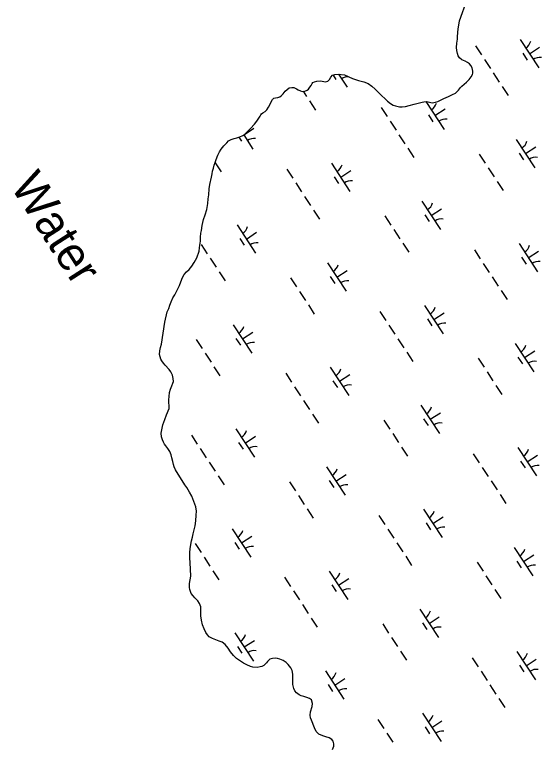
# Model space of a CAD drawing. Extents: x 3945642 to 3966284, y 206476 to 228921.
# Drawn here: x 3957251 to 3958027, y 210144 to 211224 of the extents above; entities that cross this region are included whole.
import ezdxf

# ---------------------------------------------------------------- set-up
doc = ezdxf.new("R2010")
doc.units = 0
doc.layers.add('V-RIVR-IDEN', color=7, linetype='Continuous')
doc.layers.add('V-WETL-SWMP', color=7, linetype='Continuous')

msp = doc.modelspace()

# ---------------------------------------------------------------- linework, layer by layer
at = {"layer": 'V-WETL-SWMP'}
for p, q in [((3957906.8, 211214.9), (3957917.9, 211247.1)), ((3957905.6, 211208.7), (3957906.8, 211214.9)), ((3957904.9, 211203.2), (3957905.6, 211208.7)), ((3957903.9, 211191.5), (3957904.3, 211197.7)), ((3957904.3, 211197.7), (3957904.9, 211203.2)), ((3957902.9, 211181.9), (3957903.5, 211188)), ((3957903.5, 211188), (3957903.9, 211191.5)), ((3957996, 211187.3), (3958023.4, 211145.4)), ((3957902.4, 211175.8), (3957902.9, 211181.9)), ((3957902.7, 211171), (3957902.4, 211175.8)), ((3957930.2, 211178.1), (3957939, 211164.8)), ((3958009.7, 211166.4), (3958024.7, 211176.2)), ((3957903.7, 211166.6), (3957902.7, 211171)), ((3957904.8, 211163.5), (3957903.7, 211166.6)), ((3957906.8, 211160.3), (3957904.8, 211163.5)), ((3957999.9, 211167.1), (3958006.5, 211157.1)), ((3957910.1, 211157.5), (3957906.8, 211160.3)), ((3957914.8, 211155.4), (3957910.1, 211157.5)), ((3957918.5, 211153.4), (3957914.8, 211155.4)), ((3957921.5, 211151.3), (3957918.5, 211153.4)), ((3957923.4, 211149), (3957921.5, 211151.3)), ((3957943.3, 211158.1), (3957952.1, 211144.7)), ((3957925.2, 211145.6), (3957923.4, 211149)), ((3957926.3, 211140.8), (3957925.2, 211145.6)), ((3957926.3, 211137.7), (3957926.3, 211140.8)), ((3957712.4, 211126), (3957714.7, 211128.4)), ((3957714.7, 211128.4), (3957716.7, 211131.6)), ((3957716.7, 211131.6), (3957719.4, 211134.6)), ((3957719.4, 211134.6), (3957722.9, 211135.7)), ((3957720.2, 211134.8), (3957724.3, 211128.5)), ((3957722.9, 211135.7), (3957727.7, 211136.4)), ((3957727.7, 211136.4), (3957736.9, 211135.2)), ((3957728.4, 211136.3), (3957741.2, 211116.8)), ((3957736.9, 211135.2), (3957748.7, 211129.8)), ((3957748.7, 211129.8), (3957757.9, 211127.1)), ((3957916.9, 211124.6), (3957920.9, 211128.5)), ((3957920.9, 211128.5), (3957923.7, 211132.3)), ((3957923.7, 211132.3), (3957925.9, 211135.5)), ((3957925.9, 211135.5), (3957926.3, 211137.7)), ((3957956.5, 211138), (3957965.3, 211124.6)), ((3957686.1, 211116.8), (3957687.8, 211119.5)), ((3957687.8, 211119.5), (3957689.4, 211122.4)), ((3957689.4, 211122.4), (3957690.6, 211123.9)), ((3957690.6, 211123.9), (3957692.7, 211125.1)), ((3957692.7, 211125.1), (3957696.3, 211126)), ((3957696.3, 211126), (3957701, 211126.3)), ((3957701, 211126.3), (3957704.1, 211125.7)), ((3957704.1, 211125.7), (3957708.8, 211125)), ((3957708.8, 211125), (3957712.4, 211126)), ((3957757.9, 211127.1), (3957765.5, 211124.9)), ((3957765.5, 211124.9), (3957771.9, 211122.2)), ((3957771.9, 211122.2), (3957777.5, 211118.6)), ((3957777.5, 211118.6), (3957782.1, 211114.3)), ((3957908.3, 211116.7), (3957910.2, 211118.7)), ((3957910.2, 211118.7), (3957913.3, 211121.6)), ((3957913.3, 211121.6), (3957916.9, 211124.6)), ((3957969.6, 211117.9), (3957978.4, 211104.5)), ((3957644.3, 211104.5), (3957646.4, 211107)), ((3957646.4, 211107), (3957649.7, 211110.9)), ((3957649.7, 211110.9), (3957655.7, 211115.9)), ((3957655.7, 211115.9), (3957659.5, 211116.7)), ((3957659.5, 211116.7), (3957662.3, 211116.3)), ((3957662.3, 211116.3), (3957666.4, 211114.7)), ((3957666.4, 211114.7), (3957668.9, 211113)), ((3957668.9, 211113), (3957672, 211111.5)), ((3957672, 211111.5), (3957674.6, 211110.8)), ((3957674.6, 211110.8), (3957678.5, 211111.2)), ((3957676, 211110.9), (3957681, 211103.4)), ((3957678.5, 211111.2), (3957681.9, 211112.6)), ((3957681.9, 211112.6), (3957683.9, 211114.2)), ((3957683.9, 211114.2), (3957686.1, 211116.8)), ((3957782.1, 211114.3), (3957788, 211108.2)), ((3957788, 211108.2), (3957792.1, 211104.3)), ((3957896.3, 211106), (3957900.5, 211108.3)), ((3957900.5, 211108.3), (3957905.3, 211112.7)), ((3957905.3, 211112.7), (3957908.3, 211116.7)), ((3957628.3, 211094.3), (3957630.7, 211098.9)), ((3957630.7, 211098.9), (3957632.8, 211100.6)), ((3957632.8, 211100.6), (3957635.4, 211101.4)), ((3957635.4, 211101.4), (3957638.7, 211101.8)), ((3957638.7, 211101.8), (3957641.9, 211102.8)), ((3957641.9, 211102.8), (3957644.3, 211104.5)), ((3957685.4, 211096.7), (3957694.2, 211083.3)), ((3957792.1, 211104.3), (3957796.5, 211100.2)), ((3957796.5, 211100.2), (3957800.7, 211096.5)), ((3957800.7, 211096.5), (3957805.1, 211093.1)), ((3957874.5, 211095.8), (3957878.6, 211097.8)), ((3957878.6, 211097.8), (3957883.7, 211100.2)), ((3957883.7, 211100.2), (3957890.6, 211103.1)), ((3957890.6, 211103.1), (3957896.3, 211106)), ((3957622.6, 211083.7), (3957625, 211087.3)), ((3957625, 211087.3), (3957627.1, 211090.8)), ((3957627.1, 211090.8), (3957628.3, 211094.3)), ((3957791.1, 211087), (3957799.8, 211073.6)), ((3957805.1, 211093.1), (3957808.8, 211090.7)), ((3957808.8, 211090.7), (3957812.5, 211089.3)), ((3957812.5, 211089.3), (3957818.1, 211088.2)), ((3957818.1, 211088.2), (3957822.2, 211087.8)), ((3957822.2, 211087.8), (3957826.8, 211088.5)), ((3957826.8, 211088.5), (3957832.3, 211089.8)), ((3957832.3, 211089.8), (3957839.8, 211091.9)), ((3957839.8, 211091.9), (3957851.4, 211095.1)), ((3957851.4, 211095.1), (3957854, 211095.6)), ((3957854, 211095.6), (3957858.3, 211095.7)), ((3957857.1, 211095.7), (3957884.2, 211054.3)), ((3957858.3, 211095.7), (3957862.6, 211094.7)), ((3957862.6, 211094.7), (3957866.2, 211094.1)), ((3957866.2, 211094.1), (3957871.1, 211094.8)), ((3957870.5, 211075.2), (3957885.6, 211085.1)), ((3957871.1, 211094.8), (3957874.5, 211095.8)), ((3957612.5, 211074.2), (3957613.5, 211076.1)), ((3957613.5, 211076.1), (3957614.7, 211077.6)), ((3957614.7, 211077.6), (3957616.8, 211079.2)), ((3957616.8, 211079.2), (3957619.9, 211081.2)), ((3957619.9, 211081.2), (3957622.6, 211083.7)), ((3957860.8, 211076), (3957867.4, 211066)), ((3957604.5, 211062.2), (3957607.7, 211066.9)), ((3957607.7, 211066.9), (3957612.5, 211074.2)), ((3957804.2, 211066.9), (3957813, 211053.5)), ((3957589.4, 211047.3), (3957603.4, 211056.5)), ((3957594.2, 211051.6), (3957598.4, 211055.8)), ((3957598.4, 211055.8), (3957604.5, 211062.2)), ((3957574.3, 211041.1), (3957578.2, 211042.1)), ((3957578.2, 211042.1), (3957582.6, 211043.6)), ((3957581.3, 211043.2), (3957585.2, 211037.3)), ((3957582.6, 211043.6), (3957587, 211045.5)), ((3957587, 211045.5), (3957590, 211047.7)), ((3957588.4, 211046.5), (3957602, 211025.7)), ((3957590, 211047.7), (3957594.2, 211051.6)), ((3957817.4, 211046.8), (3957826.1, 211033.5)), ((3957559, 211030.2), (3957563.4, 211035)), ((3957563.4, 211035), (3957566.2, 211037.6)), ((3957566.2, 211037.6), (3957569.8, 211039.7)), ((3957569.8, 211039.7), (3957574.3, 211041.1)), ((3957990.4, 211039.9), (3958017.8, 210998.1)), ((3957550.4, 211016.6), (3957552.7, 211021.7)), ((3957552.7, 211021.7), (3957555.3, 211025.7)), ((3957555.3, 211025.7), (3957559, 211030.2)), ((3957830.5, 211026.8), (3957839.3, 211013.4)), ((3958004.1, 211019), (3958019.2, 211028.8)), ((3957546.2, 211006), (3957547.6, 211010.1)), ((3957547.6, 211010.1), (3957550.4, 211016.6)), ((3957935.7, 211018.1), (3957944.5, 211004.7)), ((3957994.4, 211019.8), (3958001, 211009.7)), ((3957543.7, 210997.6), (3957544.8, 211001.9)), ((3957544.8, 211001.9), (3957546.2, 211006)), ((3957546.2, 211005.5), (3957555, 210992.1)), ((3957717.7, 211005), (3957745.1, 210963.1)), ((3957541, 210984), (3957542, 210989.2)), ((3957542, 210989.2), (3957542.6, 210993.1)), ((3957542.6, 210993.1), (3957543.7, 210997.6)), ((3957651.9, 210995.8), (3957660.7, 210982.5)), ((3957731.4, 210984.1), (3957746.5, 210993.9)), ((3957948.9, 210998), (3957957.7, 210984.6)), ((3957538.3, 210973.2), (3957541, 210984)), ((3957721.7, 210984.8), (3957728.2, 210974.8)), ((3957962, 210977.9), (3957970.8, 210964.5)), ((3957536.8, 210958.1), (3957537.6, 210966.9)), ((3957537.6, 210966.9), (3957538.3, 210973.2)), ((3957665.1, 210975.8), (3957673.8, 210962.4)), ((3957536.1, 210952), (3957536.8, 210958.1)), ((3957678.2, 210955.7), (3957687, 210942.3)), ((3957534, 210936.5), (3957535.7, 210945.5)), ((3957535.7, 210945.5), (3957536.1, 210952)), ((3957851.3, 210948.7), (3957878.7, 210906.9)), ((3957531.5, 210928.7), (3957534, 210936.5)), ((3957691.4, 210935.6), (3957700.1, 210922.2)), ((3957865, 210927.8), (3957880, 210937.7)), ((3957529.3, 210921.8), (3957531.5, 210928.7)), ((3957796.6, 210926.9), (3957805.4, 210913.5)), ((3957855.3, 210928.6), (3957861.8, 210918.6)), ((3957526, 210905.5), (3957527.3, 210912.7)), ((3957527.3, 210912.7), (3957529.3, 210921.8)), ((3957578.6, 210913.8), (3957606, 210872)), ((3957524.9, 210895.5), (3957525.4, 210901.5)), ((3957525.4, 210901.5), (3957526, 210905.5)), ((3957592.3, 210892.9), (3957607.3, 210902.8)), ((3957809.8, 210906.8), (3957818.5, 210893.4)), ((3957524.5, 210889.7), (3957524.9, 210895.5)), ((3957582.5, 210893.7), (3957589.1, 210883.7)), ((3957523.3, 210879.8), (3957523.6, 210883.7)), ((3957523.6, 210883.7), (3957524.5, 210889.7)), ((3957525.9, 210884.6), (3957534.7, 210871.2)), ((3957822.9, 210886.8), (3957831.7, 210873.4)), ((3957994.4, 210886.2), (3958021.8, 210844.4)), ((3957519.1, 210864.9), (3957522.5, 210875)), ((3957522.5, 210875), (3957523.3, 210879.8)), ((3957928.6, 210877.1), (3957937.3, 210863.7)), ((3958008.1, 210865.3), (3958023.1, 210875.1)), ((3957511.8, 210852.8), (3957515.5, 210858.4)), ((3957515.5, 210858.4), (3957519.1, 210864.9)), ((3957539.1, 210864.5), (3957547.8, 210851.2)), ((3957998.3, 210866.1), (3958004.9, 210856)), ((3957504.3, 210844.3), (3957508.1, 210848)), ((3957508.1, 210848), (3957511.8, 210852.8)), ((3957712.2, 210857.6), (3957739.6, 210815.8)), ((3957941.7, 210857), (3957950.5, 210843.6)), ((3957498.1, 210836.1), (3957500.7, 210840.6)), ((3957500.7, 210840.6), (3957504.3, 210844.3)), ((3957552.2, 210844.5), (3957561, 210831.1)), ((3957716.1, 210837.5), (3957722.7, 210827.4)), ((3957725.9, 210836.7), (3957740.9, 210846.5)), ((3957954.9, 210836.9), (3957963.6, 210823.5)), ((3957493.5, 210824.1), (3957495.6, 210829.6)), ((3957495.6, 210829.6), (3957498.1, 210836.1)), ((3957657.5, 210835.8), (3957666.2, 210822.4)), ((3957486.7, 210810.6), (3957490.2, 210817.3)), ((3957490.2, 210817.3), (3957493.5, 210824.1)), ((3957670.6, 210815.7), (3957679.4, 210802.3)), ((3957968, 210816.8), (3957976.8, 210803.5)), ((3957481.5, 210800.2), (3957484, 210806)), ((3957484, 210806), (3957486.7, 210810.6)), ((3957477.8, 210790.6), (3957479.6, 210795.2)), ((3957479.6, 210795.2), (3957481.5, 210800.2)), ((3957683.8, 210795.6), (3957692.5, 210782.2)), ((3957855.2, 210795), (3957882.6, 210753.2)), ((3957472.2, 210770.3), (3957475.7, 210785.5)), ((3957475.7, 210785.5), (3957477.8, 210790.6)), ((3957789.4, 210785.9), (3957798.2, 210772.5)), ((3957868.9, 210774.1), (3957884, 210784)), ((3957859.2, 210774.9), (3957865.8, 210764.9)), ((3957467.1, 210737.7), (3957472.2, 210770.3)), ((3957573, 210766.4), (3957600.4, 210724.6)), ((3957802.6, 210765.8), (3957811.4, 210752.5)), ((3957586.7, 210745.5), (3957601.8, 210755.4)), ((3957518.3, 210744.6), (3957527.1, 210731.2)), ((3957577, 210746.3), (3957583.5, 210736.3)), ((3957815.7, 210745.8), (3957824.5, 210732.4)), ((3957464.7, 210727.7), (3957465.9, 210732.6)), ((3957465.9, 210732.6), (3957467.1, 210737.7)), ((3957988.8, 210738.8), (3958016.2, 210697)), ((3957464.3, 210722.7), (3957464.7, 210727.7)), ((3957465.1, 210718.9), (3957464.3, 210722.7)), ((3957466.3, 210715.7), (3957465.1, 210718.9)), ((3957531.5, 210724.5), (3957540.2, 210711.1)), ((3957828.9, 210725.7), (3957837.7, 210712.3)), ((3957992.8, 210718.7), (3957999.3, 210708.7)), ((3958002.5, 210717.9), (3958017.6, 210727.8)), ((3957467.8, 210712.9), (3957466.3, 210715.7)), ((3957470.1, 210709.5), (3957467.8, 210712.9)), ((3957472.4, 210706.6), (3957470.1, 210709.5)), ((3957934.1, 210717), (3957942.9, 210703.6)), ((3957478.3, 210700.1), (3957472.4, 210706.6)), ((3957480.8, 210696.7), (3957478.3, 210700.1)), ((3957483.2, 210692), (3957480.8, 210696.7)), ((3957544.6, 210704.4), (3957553.4, 210691.1)), ((3957716.1, 210703.9), (3957743.5, 210662.1)), ((3957947.3, 210696.9), (3957956, 210683.5)), ((3957484.3, 210687.2), (3957483.2, 210692)), ((3957485, 210682.8), (3957484.3, 210687.2)), ((3957650.3, 210694.8), (3957659.1, 210681.4)), ((3957729.8, 210683), (3957744.8, 210692.8)), ((3957481.5, 210673.8), (3957485, 210682.8)), ((3957663.4, 210674.7), (3957672.2, 210661.3)), ((3957720, 210683.8), (3957726.6, 210673.7)), ((3957960.4, 210676.8), (3957969.2, 210663.4)), ((3957478.3, 210660.5), (3957479.1, 210666.2)), ((3957479.1, 210666.2), (3957480.4, 210671.1)), ((3957480.4, 210671.1), (3957481.5, 210673.8)), ((3957477.8, 210655.4), (3957478.3, 210660.5)), ((3957477.9, 210651.8), (3957477.8, 210655.4)), ((3957676.6, 210654.6), (3957685.4, 210641.2)), ((3957474.5, 210633.2), (3957478.3, 210642.9)), ((3957478.4, 210646.8), (3957477.9, 210651.8)), ((3957478.3, 210642.9), (3957478.4, 210646.8)), ((3957849.7, 210647.7), (3957877.1, 210605.8)), ((3957471.9, 210626.7), (3957474.5, 210633.2)), ((3957689.8, 210634.5), (3957698.5, 210621.2)), ((3957863.4, 210626.8), (3957878.4, 210636.6)), ((3957469.3, 210618.9), (3957471.9, 210626.7)), ((3957795, 210625.8), (3957803.8, 210612.4)), ((3957853.6, 210627.5), (3957860.2, 210617.5)), ((3957466.9, 210606.5), (3957467.7, 210611.4)), ((3957467.7, 210611.4), (3957469.3, 210618.9)), ((3957577, 210612.7), (3957604.3, 210570.9)), ((3957467.2, 210600.9), (3957466.9, 210606.5)), ((3957468.5, 210596.6), (3957467.2, 210600.9)), ((3957511.2, 210603.6), (3957519.9, 210590.2)), ((3957590.7, 210591.8), (3957605.7, 210601.7)), ((3957808.1, 210605.8), (3957816.9, 210592.4)), ((3957470.1, 210592.9), (3957468.5, 210596.6)), ((3957471.8, 210590.2), (3957470.1, 210592.9)), ((3957473.4, 210587.9), (3957471.8, 210590.2)), ((3957580.9, 210592.6), (3957587.5, 210582.6)), ((3957476.4, 210583.8), (3957473.4, 210587.9)), ((3957479.3, 210579.1), (3957476.4, 210583.8)), ((3957481.5, 210574.2), (3957479.3, 210579.1)), ((3957524.3, 210583.5), (3957533.1, 210570.2)), ((3957821.3, 210585.7), (3957830.1, 210572.3)), ((3957992.7, 210585.1), (3958020.1, 210543.3)), ((3957482.6, 210569.9), (3957481.5, 210574.2)), ((3957483.7, 210564.5), (3957482.6, 210569.9)), ((3957927, 210576), (3957935.7, 210562.6)), ((3958006.4, 210564.2), (3958021.5, 210574.1)), ((3957484.8, 210560.1), (3957483.7, 210564.5)), ((3957485.9, 210556.8), (3957484.8, 210560.1)), ((3957487.8, 210552.3), (3957485.9, 210556.8)), ((3957537.5, 210563.5), (3957546.2, 210550.1)), ((3957710.5, 210556.5), (3957737.9, 210514.7)), ((3957940.1, 210555.9), (3957948.9, 210542.5)), ((3957996.7, 210565), (3958003.3, 210555)), ((3957501.8, 210530.2), (3957487.8, 210552.3)), ((3957724.2, 210535.6), (3957739.3, 210545.5)), ((3957550.6, 210543.4), (3957559.4, 210530)), ((3957655.8, 210534.7), (3957664.6, 210521.3)), ((3957714.5, 210536.4), (3957721.1, 210526.4)), ((3957953.3, 210535.9), (3957962, 210522.5)), ((3957504.6, 210526.1), (3957501.8, 210530.2)), ((3957508.3, 210519.4), (3957504.6, 210526.1)), ((3957511.7, 210513.3), (3957508.3, 210519.4)), ((3957517.9, 210497.8), (3957511.7, 210513.3)), ((3957669, 210514.6), (3957677.8, 210501.2)), ((3957966.4, 210515.8), (3957975.2, 210502.4)), ((3957518.7, 210491.4), (3957517.9, 210497.8)), ((3957518.5, 210485.5), (3957518.7, 210491.4)), ((3957682.1, 210494.5), (3957690.9, 210481.1)), ((3957853.6, 210494), (3957881, 210452.2)), ((3957517.7, 210476.8), (3957518.5, 210485.5)), ((3957787.8, 210484.9), (3957796.6, 210471.5)), ((3957867.3, 210473.1), (3957882.4, 210482.9)), ((3957515.4, 210463.5), (3957516.6, 210469.6)), ((3957516.6, 210469.6), (3957517.7, 210476.8)), ((3957857.6, 210473.9), (3957864.1, 210463.8)), ((3957514, 210458), (3957515.4, 210463.5)), ((3957571.4, 210465.4), (3957598.8, 210423.5)), ((3957801, 210464.8), (3957809.7, 210451.4)), ((3957511.4, 210447.7), (3957512.9, 210453)), ((3957512.9, 210453), (3957514, 210458)), ((3957585.1, 210444.5), (3957600.2, 210454.3)), ((3957509.4, 210435.5), (3957510.3, 210441.9)), ((3957510.3, 210441.9), (3957511.4, 210447.7)), ((3957516.7, 210443.5), (3957525.5, 210430.1)), ((3957575.4, 210445.2), (3957581.9, 210435.2)), ((3957814.1, 210444.7), (3957822.9, 210431.3)), ((3957987.2, 210437.7), (3958014.6, 210395.9)), ((3957508.9, 210430.1), (3957509.4, 210435.5)), ((3957509, 210422), (3957508.9, 210430.1)), ((3958000.9, 210416.8), (3958016, 210426.7)), ((3957509.7, 210415.4), (3957509, 210422)), ((3957529.9, 210423.5), (3957538.6, 210410.1)), ((3957827.3, 210424.6), (3957836, 210411.2)), ((3957932.5, 210415.9), (3957941.3, 210402.5)), ((3957991.2, 210417.6), (3957997.7, 210407.6)), ((3957510.5, 210395.4), (3957509.7, 210415.4)), ((3957508.5, 210384.5), (3957510.5, 210395.4)), ((3957543, 210403.4), (3957551.8, 210390)), ((3957714.5, 210402.8), (3957741.9, 210361)), ((3957945.7, 210395.8), (3957954.4, 210382.5)), ((3957508.4, 210378.6), (3957508.5, 210384.5)), ((3957648.7, 210393.7), (3957657.4, 210380.3)), ((3957728.2, 210381.9), (3957743.2, 210391.8)), ((3957508.8, 210375.4), (3957508.4, 210378.6)), ((3957511.1, 210369.6), (3957508.8, 210375.4)), ((3957661.8, 210373.6), (3957670.6, 210360.2)), ((3957718.4, 210382.7), (3957725, 210372.7)), ((3957958.8, 210375.8), (3957967.6, 210362.4)), ((3957513.7, 210366.5), (3957511.1, 210369.6)), ((3957516.5, 210363.5), (3957513.7, 210366.5)), ((3957518.5, 210361.5), (3957516.5, 210363.5)), ((3957521, 210358.9), (3957518.5, 210361.5)), ((3957523.4, 210355.2), (3957521, 210358.9)), ((3957525.3, 210350), (3957523.4, 210355.2)), ((3957675, 210353.5), (3957683.7, 210340.2)), ((3957525.1, 210336.7), (3957525.4, 210342.4)), ((3957525.4, 210346.2), (3957525.3, 210350)), ((3957525.4, 210342.4), (3957525.4, 210346.2)), ((3957848.1, 210346.6), (3957875.5, 210304.8)), ((3957526.2, 210330.6), (3957525.1, 210336.7)), ((3957527.9, 210323.5), (3957526.2, 210330.6)), ((3957688.1, 210333.5), (3957696.9, 210320.1)), ((3957861.8, 210325.7), (3957876.8, 210335.5)), ((3957529.9, 210317.8), (3957527.9, 210323.5)), ((3957793.4, 210324.8), (3957802.1, 210311.4)), ((3957852, 210326.5), (3957858.6, 210316.4)), ((3957532.4, 210312.4), (3957529.9, 210317.8)), ((3957534.8, 210308.8), (3957532.4, 210312.4)), ((3957537.7, 210306), (3957534.8, 210308.8)), ((3957575.3, 210311.7), (3957602.7, 210269.8)), ((3957542.2, 210303.3), (3957537.7, 210306)), ((3957547.4, 210301.2), (3957542.2, 210303.3)), ((3957552.3, 210299.5), (3957547.4, 210301.2)), ((3957556.5, 210297.9), (3957552.3, 210299.5)), ((3957561.2, 210294.5), (3957556.5, 210297.9)), ((3957589, 210290.8), (3957604.1, 210300.6)), ((3957806.5, 210304.7), (3957815.3, 210291.3)), ((3957565.4, 210289.2), (3957561.2, 210294.5)), ((3957568.8, 210283.8), (3957565.4, 210289.2)), ((3957579.3, 210291.6), (3957585.9, 210281.5)), ((3957573.6, 210278.2), (3957568.8, 210283.8)), ((3957578, 210274), (3957573.6, 210278.2)), ((3957819.7, 210284.6), (3957828.4, 210271.2)), ((3957991.1, 210284.1), (3958018.5, 210242.2)), ((3957582.2, 210270.7), (3957578, 210274)), ((3957588, 210267), (3957582.2, 210270.7)), ((3957593.1, 210264.3), (3957588, 210267)), ((3957598.3, 210262.2), (3957593.1, 210264.3)), ((3957620.5, 210265.7), (3957618, 210263.5)), ((3957622, 210267.5), (3957620.5, 210265.7)), ((3957623.6, 210269.3), (3957622, 210267.5)), ((3957625.5, 210271.2), (3957623.6, 210269.3)), ((3957627, 210272.7), (3957625.5, 210271.2)), ((3957628.7, 210273.4), (3957627, 210272.7)), ((3957631, 210273.9), (3957628.7, 210273.4)), ((3957635, 210274.3), (3957631, 210273.9)), ((3957638.4, 210273.7), (3957635, 210274.3)), ((3957641.8, 210272.7), (3957638.4, 210273.7)), ((3957646.6, 210270.8), (3957641.8, 210272.7)), ((3957650.9, 210267.8), (3957646.6, 210270.8)), ((3957654.1, 210265), (3957650.9, 210267.8)), ((3957658.1, 210260.2), (3957654.1, 210265)), ((3957925.3, 210274.9), (3957934.1, 210261.5)), ((3958004.8, 210263.1), (3958019.9, 210273)), ((3957601.8, 210260.8), (3957598.3, 210262.2)), ((3957608.4, 210260.5), (3957601.8, 210260.8)), ((3957612.7, 210261.3), (3957608.4, 210260.5)), ((3957615.3, 210262), (3957612.7, 210261.3)), ((3957618, 210263.5), (3957615.3, 210262)), ((3957660.1, 210256.1), (3957658.1, 210260.2)), ((3957661, 210250.8), (3957660.1, 210256.1)), ((3957708.9, 210255.4), (3957736.3, 210213.6)), ((3957938.5, 210254.9), (3957947.3, 210241.5)), ((3957995.1, 210263.9), (3958001.7, 210253.9)), ((3957660.7, 210240), (3957661, 210244.5)), ((3957661, 210244.5), (3957661, 210250.8)), ((3957722.6, 210234.5), (3957737.7, 210244.4)), ((3957660.9, 210235.4), (3957660.7, 210240)), ((3957662.1, 210229.4), (3957660.9, 210235.4)), ((3957712.9, 210235.3), (3957719.5, 210225.3)), ((3957951.6, 210234.8), (3957960.4, 210221.4)), ((3957663.6, 210226), (3957662.1, 210229.4)), ((3957666.1, 210223.1), (3957663.6, 210226)), ((3957670.1, 210220), (3957666.1, 210223.1)), ((3957673.3, 210218.7), (3957670.1, 210220)), ((3957677.2, 210217.5), (3957673.3, 210218.7)), ((3957681.7, 210216.3), (3957677.2, 210217.5)), ((3957685.5, 210214.9), (3957681.7, 210216.3)), ((3957688.2, 210212.8), (3957685.5, 210214.9)), ((3957689.7, 210207.6), (3957688.2, 210212.8)), ((3957964.8, 210214.7), (3957973.6, 210201.3)), ((3957686.9, 210195.2), (3957689.5, 210203.2)), ((3957689.5, 210203.2), (3957689.7, 210207.6)), ((3957686.3, 210190.2), (3957686.9, 210195.2)), ((3957687, 210186), (3957686.3, 210190.2)), ((3957852, 210192.9), (3957879.4, 210151.1)), ((3957688.5, 210182.6), (3957687, 210186)), ((3957692.8, 210171.6), (3957688.5, 210182.6)), ((3957786.2, 210183.8), (3957795, 210170.4)), ((3957865.7, 210172), (3957880.7, 210181.9)), ((3957695.4, 210166.1), (3957692.8, 210171.6)), ((3957855.9, 210172.8), (3957862.5, 210162.7)), ((3957699.3, 210162), (3957695.4, 210166.1)), ((3957704.9, 210159.5), (3957699.3, 210162)), ((3957709.7, 210158.2), (3957704.9, 210159.5)), ((3957714.4, 210156.8), (3957709.7, 210158.2)), ((3957718.2, 210154.5), (3957714.4, 210156.8)), ((3957799.3, 210163.7), (3957808.1, 210150.3)), ((3957720.4, 210151.9), (3957718.2, 210154.5)), ((3957721.5, 210148.1), (3957720.4, 210151.9)), ((3957721.4, 210144.6), (3957721.5, 210148.1)), ((3957719.2, 210139.3), (3957721.4, 210144.6))]:
    msp.add_line(p, q, dxfattribs=at)
for centre, start, end in [((3957994.7, 211189.6), 302.4575, 344.0011), ((3958025, 211143.4), 82.4574, 124.0011), ((3957742.8, 211114.8), 89.0611, 124.0011), ((3957855.6, 211098.4), 302.4575, 344.0011), ((3957885.9, 211052.2), 82.4574, 124.0011), ((3957603.7, 211023.6), 82.4574, 124.0011), ((3957989.2, 211042.2), 302.4575, 344.0011), ((3958019.5, 210996), 82.4574, 124.0011), ((3957716.5, 211007.3), 302.4575, 344.0011), ((3957746.7, 210961.1), 82.4574, 124.0011), ((3957850.1, 210951.1), 302.4575, 344.0011), ((3957880.3, 210904.9), 82.4574, 124.0011), ((3957577.3, 210916.1), 302.4575, 344.0011), ((3957607.6, 210869.9), 82.4574, 124.0011), ((3957993.1, 210888.5), 302.4575, 344.0011), ((3958023.4, 210842.3), 82.4574, 124.0011), ((3957710.9, 210859.9), 302.4575, 344.0011), ((3957741.2, 210813.7), 82.4574, 124.0011), ((3957854, 210797.4), 302.4575, 344.0011), ((3957571.8, 210768.8), 302.4575, 344.0011), ((3957884.3, 210751.2), 82.4574, 124.0011), ((3957602.1, 210722.5), 82.4574, 124.0011), ((3957987.6, 210741.1), 302.4575, 344.0011), ((3958017.8, 210694.9), 82.4574, 124.0011), ((3957714.9, 210706.2), 302.4575, 344.0011), ((3957745.1, 210660), 82.4574, 124.0011), ((3957848.4, 210650), 302.4575, 344.0011), ((3957878.7, 210603.8), 82.4574, 124.0011), ((3957575.7, 210615.1), 302.4575, 344.0011), ((3957606, 210568.9), 82.4574, 124.0011), ((3957991.5, 210587.4), 302.4575, 344.0011), ((3958021.8, 210541.2), 82.4574, 124.0011), ((3957709.3, 210558.8), 302.4575, 344.0011), ((3957739.6, 210512.6), 82.4574, 124.0011), ((3957852.4, 210496.3), 302.4575, 344.0011), ((3957570.2, 210467.7), 302.4575, 344.0011), ((3957882.6, 210450.1), 82.4574, 124.0011), ((3957600.4, 210421.5), 82.4574, 124.0011), ((3957986, 210440.1), 302.4575, 344.0011), ((3958016.2, 210393.9), 82.4574, 124.0011), ((3957713.2, 210405.1), 302.4575, 344.0011), ((3957743.5, 210358.9), 82.4574, 124.0011), ((3957846.8, 210348.9), 302.4575, 344.0011), ((3957877.1, 210302.7), 82.4574, 124.0011), ((3957574.1, 210314), 302.4575, 344.0011), ((3957604.4, 210267.8), 82.4574, 124.0011), ((3957989.9, 210286.4), 302.4575, 344.0011), ((3958020.2, 210240.2), 82.4574, 124.0011), ((3957707.7, 210257.8), 302.4575, 344.0011), ((3957738, 210211.6), 82.4574, 124.0011), ((3957850.8, 210195.2), 302.4575, 344.0011), ((3957881, 210149), 82.4574, 124.0011)]:
    msp.add_arc(centre, 17.6, start, end, dxfattribs=at)

# ---------------------------------------------------------------- texts
at = {"layer": 'V-RIVR-IDEN'}
msp.add_text('Water', height=50, rotation=302.6757, dxfattribs=at).set_placement((3957243.2, 210971.3))

doc.saveas('drawing.dxf')
